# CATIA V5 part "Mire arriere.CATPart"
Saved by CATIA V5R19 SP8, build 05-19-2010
Part number: Mire arriere
Bounding box of the stored display mesh (mm): x -11.95 to 11.95, y -3.5 to 3.5, z 0 to 5
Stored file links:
  C:\Users\Arthur\Desktop\Catia parts\GLOCK\Ensemble culasse\Mire arriere.CATPart
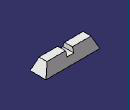
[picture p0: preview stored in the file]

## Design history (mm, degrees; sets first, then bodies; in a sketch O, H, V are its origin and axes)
Set1
  Sketch1 on xy-plane, origin (0, 0, 0), H (1, 0, 0), V (0, 1, 0)
    line L1 (11.95, 3.5) -> (11.95, -3.5)
    line L2 (11.95, -3.5) -> (-11.95, -3.5)
    line L3 (-11.95, -3.5) -> (-11.95, 3.5)
    line L4 (-11.95, 3.5) -> (11.95, 3.5)
    length L1 = 7
    length L4 = 23.9
    vertical: L1 V, L3 V
    horizontal: L2 H, L4 H
    equidistance: L1 L3 O, L2 L4 O
  Plane1: type Offset, RefPlane xy-plane, Offset 5
  Sketch2 on Plane1, origin (0, 0, 5), H (1, 0, 0), V (0, 1, 0)
    line L1 (9.75, 1.75) -> (9.75, -1.75)
    line L2 (9.75, -1.75) -> (-9.75, -1.75)
    line L3 (-9.75, -1.75) -> (-9.75, 1.75)
    line L4 (-9.75, 1.75) -> (9.75, 1.75)
    length L1 = 3.5
    length L2 = 19.5
    vertical: L1 V, L3 V
    horizontal: L2 H, L4 H
    equidistance: L1 L3 O, L2 L4 O
Body1 (main body)
  Loft1: solid, Sections (Sketch2; Sketch1)
  Sketch3 on face of Loft1, origin (0, 0, 5), H (1, 0, 0), V (0, 1, 0)
    line L1 (1.5, 2.5) -> (1.5, -2.5)
    line L2 (1.5, -2.5) -> (-1.5, -2.5)
    line L3 (-1.5, -2.5) -> (-1.5, 2.5)
    line L4 (-1.5, 2.5) -> (1.5, 2.5)
    length L1 = 5
    length L4 = 3
    vertical: L1 V, L3 V
    horizontal: L2 H, L4 H
    equidistance: L1 L3 O, L2 L4 O
  Pocket1: profile Sketch3, direction (0, 0, -1), length 2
